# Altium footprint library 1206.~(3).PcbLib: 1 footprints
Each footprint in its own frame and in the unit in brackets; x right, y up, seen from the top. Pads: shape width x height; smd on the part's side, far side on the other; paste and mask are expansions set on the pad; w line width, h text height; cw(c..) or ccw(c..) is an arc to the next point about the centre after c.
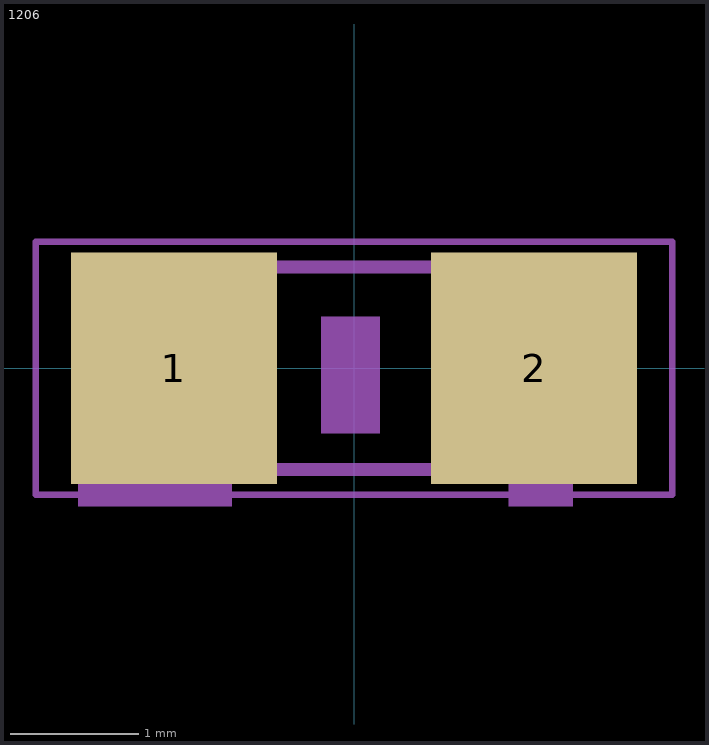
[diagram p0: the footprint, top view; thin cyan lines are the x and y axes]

## 1206 [mm]
pads (2):
  rect 1.6x1.8 smd: 1(-1.4,0) 2(1.4,0)
Mechanical 1:
  region: -2.143,0.849 -0.952,0.849 -0.952,-1.071 -2.143,-1.071
  region: 1.202,0.851 1.702,0.851 1.702,-1.073 1.202,-1.073
  region: -0.253,0.4 0.2,0.4 0.2,-0.507 -0.253,-0.507
  lines w0.051: -2.473,-0.983 2.473,-0.983 2.473,0.983 -2.473,0.983 -2.473,-0.983
  lines w0.102: -0.965,-0.787 0.965,-0.787 ; -0.965,0.787 0.965,0.787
